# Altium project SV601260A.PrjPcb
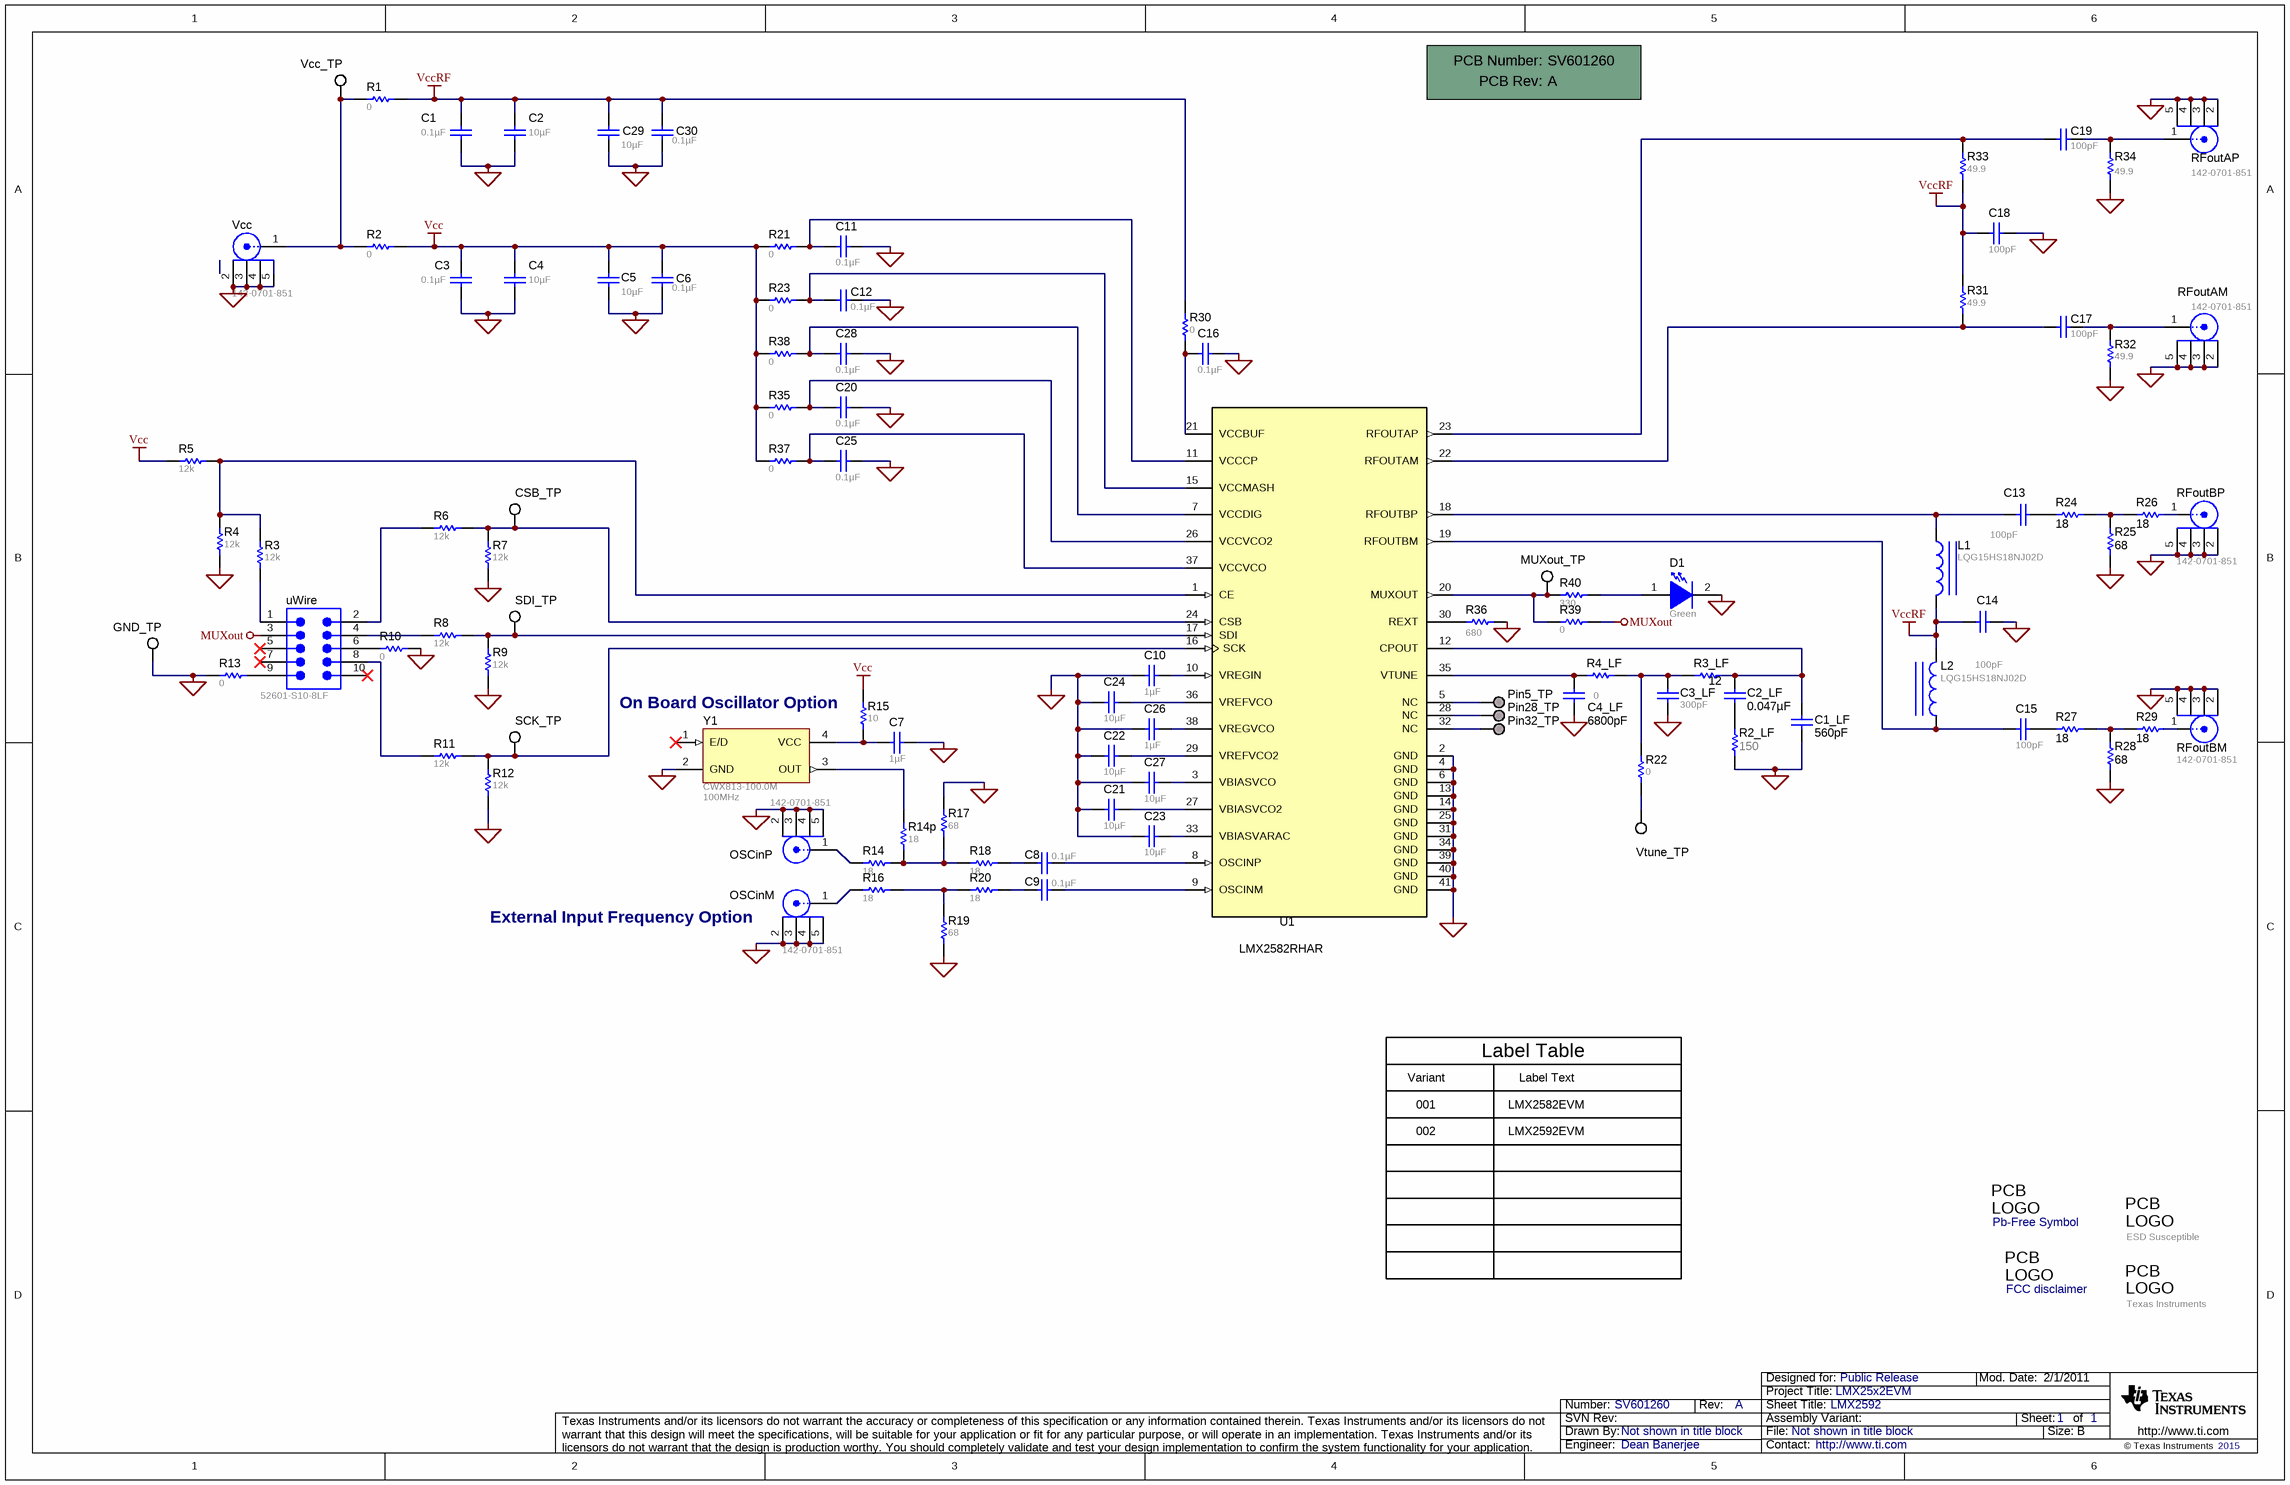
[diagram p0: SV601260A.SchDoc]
TechSupport: http://www.ti.com; SCH_Rev: A; PRJ_Title: LMX25x2EVM; PRJ_Number: SV601260; PRJ_Engineer: Dean Banerjee; PRJ_Customer: Public Release; PCB_Rev: A; PCB_Layout: Dean Banerjee; CopyrightYear: 2015
1 sheet, 106 parts. Net scope: global (net labels, ports and power ports of the same name join across sheets).
Board file: SV601260A.PcbDoc

## Sheet SV601260A.SchDoc: LMX2592
size 431 x 279 mm; Date: Not shown in title block; ApprovedBy: Not shown in title block; CheckedBy: Not shown in title block; Author: Not shown in title block; CompanyName: Not shown in title block; DrawnBy: Not shown in title block; Engineer: Not shown in title block; Organization: Not shown in title block; Address1: Not shown in title block; Address2: Not shown in title block; Address3: Not shown in title block; Address4: Not shown in title block; DocumentNumber: 1; Revision: Use project parameter SCH_Rev; SheetNumber: 1; SheetTotal: 1; PageSetup: Record=PageOptions¦CenterHorizontal=True¦CenterVertical=True¦PrintScale=0.72¦XCorrection=1.00¦YCorrection=1.00¦PrintKind=0¦BorderSize=5000000¦LeftOffset=0¦BottomOffset=0¦Orientation=2¦PaperLength=1000¦PaperWidth=1000¦Scale=100¦PaperSource=15¦PrintQuality=600¦MediaType=1¦DitherType=10¦PrintScaleMode=1¦PaperKind=Legal (8.5 x 14")¦PaperIndex=5

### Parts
!PCB  Printed Circuit Board  (value not drawn)  (mechanical)
C1  ValueDisplayed: 0.1µF  [0603]  (hidden comment: 0603YC104JAT2A)
C1_LF  ValueDisplayed: 560pF  [0603]  (hidden comment: C0603C561K5RACTU)
C2  ValueDisplayed: 10µF  [0805]  (hidden comment: C0805C106K8PACTU)
C2_LF  ValueDisplayed: 0.047µF  [0603]  (hidden comment: GRM188R71H473KA61D)
C3  ValueDisplayed: 0.1µF  [0603]  (hidden comment: 0603YC104JAT2A)
C3_LF  ValueDisplayed: 300pF  [0603]  (hidden comment: GRM1885C2A301JA01D)
C4  ValueDisplayed: 10µF  [0805]  (hidden comment: C0805C106K8PACTU)
C4_LF  ValueDisplayed: 6800pF  [0603]  (hidden comment: GRM188R71H682KA01D)
C5  ValueDisplayed: 10µF  [0805]  (hidden comment: C0805C106K8PACTU)
C6  ValueDisplayed: 0.1µF  [0603]  (hidden comment: 0603YC104JAT2A)
C7  ValueDisplayed: 1µF  [0603]  (hidden comment: C1608X7R1C105K)
C8  ValueDisplayed: 0.1µF  [0603L]  (hidden comment: 0603YC104JAT2A)
C9  ValueDisplayed: 0.1µF  [0603L]  (hidden comment: 0603YC104JAT2A)
C10  ValueDisplayed: 1µF  [0603L]  (hidden comment: C1608X7R1C105K)
C11  ValueDisplayed: 0.1µF  [0603L]  (hidden comment: 0603YC104JAT2A)
C12  ValueDisplayed: 0.1µF  [0603L]  (hidden comment: 0603YC104JAT2A)
C13  ValueDisplayed: 100pF  [0402]  (hidden comment: GRM1535C1H101JDD5D)
C14  ValueDisplayed: 100pF  [0402]  (hidden comment: GRM1535C1H101JDD5D)
C15  ValueDisplayed: 100pF  [0402]  (hidden comment: GRM1535C1H101JDD5D)
C16  ValueDisplayed: 0.1µF  [0603L]  (hidden comment: 0603YC104JAT2A)
C17  ValueDisplayed: 100pF  [0402]  (hidden comment: GRM1535C1H101JDD5D)
C18  ValueDisplayed: 100pF  [0402]  (hidden comment: GRM1535C1H101JDD5D)
C19  ValueDisplayed: 100pF  [0402]  (hidden comment: GRM1535C1H101JDD5D)
C20  ValueDisplayed: 0.1µF  [0603L]  (hidden comment: 0603YC104JAT2A)
C21  ValueDisplayed: 10µF  [0603]  (hidden comment: C1608X5R1A106M)
C22  ValueDisplayed: 10µF  [0603]  (hidden comment: C1608X5R1A106M)
C23  ValueDisplayed: 10µF  [0603]  (hidden comment: C1608X5R1A106M)
C24  ValueDisplayed: 10µF  [0603]  (hidden comment: C1608X5R1A106M)
C25  ValueDisplayed: 0.1µF  [0603]  (hidden comment: 0603YC104JAT2A)
C26  ValueDisplayed: 1µF  [0603]  (hidden comment: C1608X5R0J105K)
C27  ValueDisplayed: 10µF  [0603]  (hidden comment: C1608X5R1A106M)
C28  ValueDisplayed: 0.1µF  [0603L]  (hidden comment: 0603YC104JAT2A)
C29  ValueDisplayed: 10µF  [0805]  (hidden comment: C0805C106K8PACTU)
C30  ValueDisplayed: 0.1µF  [0603]  (hidden comment: 0603YC104JAT2A)
CSB_TP  5007  [Keystone5007]  (value not drawn)
D1  value Green  [LED_LTST-C190]  (hidden comment: LTST-C190GKT)
GND_TP  5007  [Keystone5007]  (value not drawn)
L1  LQG15HS18NJ02D  [IND_LQG15H]
L2  LQG15HS18NJ02D  [IND_LQG15H]
Logo1  ESD Susceptible  [ESD_Overlay_Small]  (no BOM)
Logo2  Texas Instruments  [TI_Stacked_Overlay_Small_Vertical]  (no BOM)
Logo3  Pb-Free Symbol  [Pb-Free_Overlay_Medium]  (no BOM)
Logo4  FCC disclaimer  [FCC_disclaimer]  (no BOM)
MUXout_TP  5007  [Keystone5007]  (value not drawn)
OSCinM  142-0701-851  [Emerson_142-0701-851]
OSCinP  142-0701-851  [Emerson_142-0701-851]
Pin5_TP  TESTPOINT  [TP_25MIL-SMT]  (value not drawn)  (no BOM)
Pin28_TP  TESTPOINT  [TP_25MIL-SMT]  (value not drawn)  (no BOM)
Pin32_TP  TESTPOINT  [TP_25MIL-SMT]  (value not drawn)  (no BOM)
R1  value 0  [0603]  (hidden comment: CRCW06030000Z0EA)
R2  value 0  [0603]  (hidden comment: CRCW06030000Z0EA)
R2_LF  ValueDisplayed: 150  [0603]  (hidden comment: CRCW0603150RJNEA)
R3  value 12k  [0603]  (hidden comment: CRCW060312K0JNEA)
R3_LF  ValueDisplayed: 12  [0603]  (hidden comment: CRCW060312R0JNEA)
R4  value 12k  [0603]  (hidden comment: CRCW060312K0JNEA)
R4_LF  value 0  [0603]  (hidden comment: CRCW06030000Z0EA)
R5  value 12k  [0603]  (hidden comment: CRCW060312K0JNEA)
R6  value 12k  [0603]  (hidden comment: CRCW060312K0JNEA)
R7  value 12k  [0603]  (hidden comment: CRCW060312K0JNEA)
R8  value 12k  [0603]  (hidden comment: CRCW060312K0JNEA)
R9  value 12k  [0603]  (hidden comment: CRCW060312K0JNEA)
R10  value 0  [0603]  (hidden comment: CRCW06030000Z0EA)
R11  value 12k  [0603]  (hidden comment: CRCW060312K0JNEA)
R12  value 12k  [0603]  (hidden comment: CRCW060312K0JNEA)
R13  value 0  [0603]  (hidden comment: CRCW06030000Z0EA)
R14  value 18  [0603]  (hidden comment: CRCW060318R0JNEA)
R14p  value 18  [0603]  (hidden comment: CRCW060318R0JNEA)
R15  value 10  [0603]  (hidden comment: CRCW060310R0JNEA)
R16  value 18  [0603]  (hidden comment: CRCW060318R0JNEA)
R17  value 68  [0603]  (hidden comment: CRCW060368R0JNEA)
R18  value 18  [0603]  (hidden comment: CRCW060318R0JNEA)
R19  value 68  [0603]  (hidden comment: CRCW060368R0JNEA)
R20  value 18  [0603]  (hidden comment: CRCW060318R0JNEA)
R21  value 0  [0603L]  (hidden comment: CRCW06030000Z0EA)
R22  value 0  [0603]  (hidden comment: CRCW06030000Z0EA)
R23  value 0  [0603L]  (hidden comment: CRCW06030000Z0EA)
R24  ValueDisplayed: 18  [0402]  (hidden comment: CRCW040218R0JNED)
R25  ValueDisplayed: 68  [0402L]  (hidden comment: CRCW040268R0JNED)
R26  ValueDisplayed: 18  [0402]  (hidden comment: CRCW040218R0JNED)
R27  ValueDisplayed: 18  [0402]  (hidden comment: CRCW040218R0JNED)
R28  ValueDisplayed: 68  [0402L]  (hidden comment: CRCW040268R0JNED)
R29  ValueDisplayed: 18  [0402]  (hidden comment: CRCW040218R0JNED)
R30  value 0  [0603L]  (hidden comment: CRCW06030000Z0EA)
R31  ValueDisplayed: 49.9  [0402L]  (hidden comment: CRCW040249R9FKED)
R32  ValueDisplayed: 49.9  [0402L]  (hidden comment: CRCW040249R9FKED)
R33  ValueDisplayed: 49.9  [0402L]  (hidden comment: CRCW040249R9FKED)
R34  ValueDisplayed: 49.9  [0402L]  (hidden comment: CRCW040249R9FKED)
R35  value 0  [0603L]  (hidden comment: CRCW06030000Z0EA)
R36  ValueDisplayed: 680  [0603]  (hidden comment: RC0603FR-07680RL)
R37  value 0  [0603]  (hidden comment: CRCW06030000Z0EA)
R38  value 0  [0603L]  (hidden comment: CRCW06030000Z0EA)
R39  value 0  [0603]  (hidden comment: CRCW06030000Z0EA)
R40  value 330  [0603]  (hidden comment: RC0603JR-07330RL)
RFoutAM  142-0701-851  [Emerson_142-0701-851]
RFoutAP  142-0701-851  [Emerson_142-0701-851]
RFoutBM  142-0701-851  [Emerson_142-0701-851]
RFoutBP  142-0701-851  [Emerson_142-0701-851]
SCK_TP  5007  [Keystone5007]  (value not drawn)
SDI_TP  5007  [Keystone5007]  (value not drawn)
U1  LMX2582RHAR  [RHA0040C]
uWire  52601-S10-8LF  [FCI_52601-S10-8LF]
Vcc  142-0701-851  [Emerson_142-0701-851]
Vcc_TP  5007  [Keystone5007]  (value not drawn)
Vtune_TP  5007  [Keystone5007]  (value not drawn)
Y1  CWX813-100.0M  Frequency: 100MHz  [OSC_CWX]

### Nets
GND: C1.1 C1_LF.2 C2.1 C3.1 C3_LF.2 C4.1 C4_LF.1 C5.1 C6.1 C7.2 C10.1 C11.1 C12.1 C14.1 C16.1 C18.1 C20.1 C21.2 C22.2 C23.2 C24.2 C25.1 C26.2 C27.1 C28.2 C29.1 C30.1 D1.2(K) GND_TP.1 OSCinM.2 OSCinM.3 OSCinM.4 OSCinM.5 OSCinP.2 OSCinP.3 OSCinP.4 OSCinP.5 R2_LF.2 R4.1 R7.1 R9.1 R10.1 R12.1 R13.2 R17.2 R19.1 R25.1 R28.2 R32.2 R34.1 R36.2 RFoutAM.2 RFoutAM.3 RFoutAM.4 RFoutAM.5 RFoutAP.2 RFoutAP.3 RFoutAP.4 RFoutAP.5 RFoutBM.2 RFoutBM.3 RFoutBM.4 RFoutBM.5 RFoutBP.2 RFoutBP.3 RFoutBP.4 RFoutBP.5 U1.2(GND) U1.4(GND) U1.6(GND) U1.13(GND) U1.14(GND) U1.25(GND) U1.31(GND) U1.34(GND) U1.39(GND) U1.40(GND) U1.41(GND) Vcc.2 Vcc.3 Vcc.4 Vcc.5 Y1.2(GND)
MUXout: R39.1 uWire.3
Vcc: C3.2 C4.2 C5.2 C6.2 R2.2 R5.1 R15.2 R21.1 R23.1 R35.2 R37.2 R38.1
VccRF: C1.2 C2.2 C14.2 C18.2 C29.2 C30.2 L1.2 L2.2 R1.2 R30.1 R31.2 R33.1
NetC1_LF_1: C1_LF.1 C2_LF.1 R3_LF.1 U1.12(CPOUT)
NetC2_LF_2: C2_LF.2 R2_LF.1
NetC3_LF_1: C3_LF.1 R3_LF.2 R4_LF.2 R22.1
NetC4_LF_2: C4_LF.2 R4_LF.1 U1.35(VTUNE)
NetC7_1: C7.1 R15.1 Y1.4(VCC)
NetC8_1: C8.1 R18.2
NetC8_2: C8.2 U1.8(OSCINP)
NetC9_1: C9.1 R20.1
NetC9_2: C9.2 U1.9(OSCINM)
NetC10_2: C10.2 U1.10(VREGIN)
NetC11_2: C11.2 R21.2 U1.11(VCCCP)
NetC12_2: C12.2 R23.2 U1.15(VCCMASH)
NetC13_1: C13.1 R24.2
NetC13_2: C13.2 L1.1 U1.18(RFOUTBP)
NetC15_1: C15.1 R27.2
NetC15_2: C15.2 L2.1 U1.19(RFOUTBM)
NetC16_2: C16.2 R30.2 U1.21(VCCBUF)
NetC17_1: C17.1 R32.1 RFoutAM.1
NetC17_2: C17.2 R31.1 U1.22(RFOUTAM)
NetC19_1: C19.1 R34.2 RFoutAP.1
NetC19_2: C19.2 R33.2 U1.23(RFOUTAP)
NetC20_2: C20.2 R35.1 U1.26(VCCVCO2)
NetC21_1: C21.1 U1.27(VBIASVCO2)
NetC22_1: C22.1 U1.29(VREFVCO2)
NetC23_1: C23.1 U1.33(VBIASVARAC)
NetC24_1: C24.1 U1.36(VREFVCO)
NetC25_2: C25.2 R37.1 U1.37(VCCVCO)
NetC26_1: C26.1 U1.38(VREGVCO)
NetC27_2: C27.2 U1.3(VBIASVCO)
NetC28_1: C28.1 R38.2 U1.7(VCCDIG)
NetCSB_TP_1: CSB_TP.1 R6.2 R7.2 U1.24(CSB)
NetD1_1: D1.1(A) R40.1
NetMUXout_TP_1: MUXout_TP.1 R39.2 R40.2 U1.20(MUXOUT)
NetOSCinM_1: OSCinM.1 R16.1
NetOSCinP_1: OSCinP.1 R14.1
NetPin5_TP_1: Pin5_TP.1 U1.5(NC)
NetPin28_TP_1: Pin28_TP.1 U1.28(NC)
NetPin32_TP_1: Pin32_TP.1 U1.32(NC)
NetR1_1: R1.1 R2.1 Vcc.1 Vcc_TP.1
NetR3_1: R3.1 uWire.1
NetR3_2: R3.2 R4.2 R5.2 U1.1(CE)
NetR6_1: R6.1 uWire.2
NetR8_1: R8.1 R9.2 SDI_TP.1 U1.17(SDI)
NetR8_2: R8.2 uWire.4
NetR10_2: R10.2 uWire.6
NetR11_1: R11.1 uWire.8
NetR11_2: R11.2 R12.2 SCK_TP.1 U1.16(SCK)
NetR13_1: R13.1 uWire.9
NetR14_2: R14.2 R14p.1 R17.1 R18.1
NetR14p_2: R14p.2 Y1.3(OUT)
NetR16_2: R16.2 R19.2 R20.2
NetR22_2: R22.2 Vtune_TP.1
NetR24_1: R24.1 R25.2 R26.2
NetR26_1: R26.1 RFoutBP.1
NetR27_1: R27.1 R28.1 R29.2
NetR29_1: R29.1 RFoutBM.1
NetR36_1: R36.1 U1.30(REXT)

Not connected (* = marked no-connect by the designer): uWire 5* 7* 10*; Y1 1(E/D)*

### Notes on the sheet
- On Board Oscillator Option
- (near OSCinM) External Input Frequency Option
- Variant
- 001
- Label Table
- Label Text
- LMX2582EVM
- 002
- LMX2592EVM

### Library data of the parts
!PCB = PCB: Manufacturer: Any; PartNumber: SV601260; SymbolCreator: a0412235
C1 C3 C6 C25 C30 = 0603YC104JAT2A: CAP, CERM, 0.1uF, 16V, +/-5%, X7R, 0603; Manufacturer: AVX; ESR_Ohm: 0.039; Polarized: N; TaMax_C: 125; TaMin_C: -55; Tolerance_%: 5; VDC_V: 16; Cap_F: 0.0000001; CompType: Capacitor; Value1: 0.039 ohm; U/M: EA
C1_LF = C0603C561K5RACTU: CAP, CERM, 560 pF, 50 V, +/- 10%, X7R, 0603; Manufacturer: Kemet; Polarized: N; TaMax_C: 125; TaMin_C: -55; Tolerance_%: 10; VDC_V: 50; Cap_F: 0.00000000056; CompType: Capacitor; Value: 560pF; Value1: Unknown; Value2: 50V; U/M: EA
C2 C4 C5 C29 = C0805C106K8PACTU: CAP, CERM, 10uF, 10V, +/-10%, X5R, 0805; Manufacturer: Kemet; ESR_Ohm: 0.003; IRMS_A: 11.43; Polarized: N; TaMax_C: 85; TaMin_C: -55; Tolerance_%: 10; Cap_F: 0.00001; CompType: Capacitor; U/M: EA; Value1: 0.003 ohm
C2_LF = GRM188R71H473KA61D: CAP, CERM, 0.047 µF, 50 V, +/- 10%, X7R, 0603; Manufacturer: MuRata; Polarized: N; TaMax_C: 125; TaMin_C: -55; Tolerance_%: 10; VDC_V: 50; Cap_F: 0.000000047; CompType: Capacitor; Value: 0.047uF; Value1: Unknown; Value2: 50V; U/M: EA
C3_LF = GRM1885C2A301JA01D: CAP, CERM, 300pF, 100V, +/-5%, C0G/NP0, 0603; Manufacturer: MuRata; Polarized: N; TaMax_C: 125; TaMin_C: -55; Tolerance_%: 5; VDC_V: 100; Cap_F: 0.0000000003; CompType: Capacitor; Value1: Unknown; U/M: EA
C4_LF = GRM188R71H682KA01D: CAP, CERM, 6800 pF, 50 V, +/- 10%, X7R, 0603; Manufacturer: MuRata; Polarized: N; TaMax_C: 125; TaMin_C: -55; Tolerance_%: 10; VDC_V: 50; Cap_F: 0.0000000068; CompType: Capacitor; Value: 6800pF; Value1: Unknown; Value2: 50V; U/M: EA
C7 = C1608X7R1C105K: CAP, CERM, 1uF, 16V, +/-10%, X7R, 0603; Manufacturer: TDK; ESR_Ohm: 0.0057; Polarized: N; TaMax_C: 125; TaMin_C: -55; Tolerance_%: 10; VDC_V: 16; Cap_F: 0.000001; CompType: Capacitor; U/M: EA; Value1: 0.0057 ohm
C8 C9 C11 C12 C16 C20 C28 = 0603YC104JAT2A: CAP, CERM, 0.1uF, 16V, +/-5%, X7R, 0603; Manufacturer: AVX; Cap_Case: 0603; ESR_Ohm: 0.039; Polarized: N; TaMax_C: 125; TaMin_C: -55; Tolerance_%: 5; VDC_V: 16; Cap_F: 0.0000001; CompType: Capacitor; Value1: 0.039 ohm; U/M: EA
C10 = C1608X7R1C105K: CAP, CERM, 1uF, 16V, +/-10%, X7R, 0603; Manufacturer: TDK; Polarized: N; CompType: Capacitor; U/M: EA; Cap_F: 0.000001; Tolerance_%: 10; ESR_Ohm: 0.0057; Value1: 0.0057 ohm; VDC_V: 16; TaMin_C: -55; TaMax_C: 125; Cap_Case: 0603
C13-C15 C17-C19 = GRM1535C1H101JDD5D: CAP, CERM, 100 pF, 50 V, +/- 5%, C0G/NP0, 0402; Manufacturer: MuRata; Polarized: N; CompType: Capacitor; Value: 100pF; U/M: EA; Cap_F: 0.0000000001; Tolerance_%: 5; Value1: Unknown; VDC_V: 50; Value2: 50V; TaMin_C: -55; TaMax_C: 125
C21-C24 C27 = C1608X5R1A106M: CAP, CERM, 10uF, 10V, +/-10%, C0G/NP0, 0603; Manufacturer: TDK; ESR_Ohm: 0.0078; IRMS_A: 1.85; Polarized: N; TaMax_C: 85; TaMin_C: -55; Tolerance_%: 10; Cap_F: 0.00001; CompType: Capacitor; U/M: EA; Value1: 0.0078 ohm
C26 = C1608X5R0J105K: CAP, CERM, 1 µF, 6.3 V, +/- 10%, X5R, 0603; Manufacturer: TDK; ESR_ohm: 0.0057; Polarized: N; TaMax_C: 85; TaMin_C: -55; Tolerance_%: 10; VDC_V: 6.3; Cap_F: 0.000001; CompType: Capacitor; Value: 1uF; U/M: EA; Value1: 0.0057 ohm; Value2: 6.3V
CSB_TP GND_TP MUXout_TP SCK_TP SDI_TP Vcc_TP Vtune_TP = 5007: Test Point, Compact, White, TH; Manufacturer: Keystone; CompType: Test Point Loop; U/M: EA
D1 = LTST-C190GKT: LED, Green, SMD; Manufacturer: Lite-On; Vf_V: 2.1; Value2: 2.1V; Io_A: 0.02; Power_TotalModule: 0.1; Value1: 0.1W; U/M: EA
L1 L2 = LQG15HS18NJ02D: Inductor, Multilayer, Air Core, 18 nH, 0.3 A, 0.36 ohm, SMD; Manufacturer: MuRata; Value: 18nH; Ind_H: 18.0E-9; Imax_A: 0.3; Irms: 0.3A @ C rise; Isat: 0.3A @ % inductance drop; DCR_ohm: 0.36; Value2: 0.3A
Logo1 = ESD_Susceptible: ESD Susceptible Symbol; SymbolCreator: codlsc
Logo2 = TI_Logo: Texas Instrument Corporate Signature; SymbolCreator: codlsc
Logo3 = Pb-Free: SymbolCreator: a0412235
Logo4 = FCC_disclaimer: SymbolCreator: codlsc
OSCinM OSCinP RFoutAM RFoutAP RFoutBM RFoutBP Vcc = 142-0701-851: Connector, SMT, End launch SMA 50 ohm; Manufacturer: Emerson Network Power Connectivity; U/M: EA
Pin5_TP Pin28_TP Pin32_TP = TESTPOINT: TEST POINT.  No entry in BOM.
R1 R2 R4_LF R10 R13 R21-R23 R30 R35 R37-R39 = CRCW06030000Z0EA: RES, 0 ohm, 5%, 0.1W, 0603; Manufacturer: Vishay-Dale; CompType: Resistor; Tolerance_%: 5; VDC_V: 75; Power_W: 0.1; U/M: EA; Value_Code: 0000; EIA_Code: E24
R2_LF = CRCW0603150RJNEA: RES, 150, 5%, 0.1 W, 0603; Manufacturer: Vishay-Dale; CompType: Resistor; Tolerance_%: 5; VDC_V: 75; Power_W: 0.1; Value: 150; U/M: EA; Value_Code: 150R; Value2: 0.1W; TempCo: 200 ppm/C; EIA_Code: E24
R3-R9 R11 R12 = CRCW060312K0JNEA: RES, 12k ohm, 5%, 0.1W, 0603; Manufacturer: Vishay-Dale; CompType: Resistor; Tolerance_%: 5; VDC_V: 75; Power_W: 0.1; Res_ohm: 12000; U/M: EA; Value_Code: 12k0; EIA_Code: E24
R3_LF = CRCW060312R0JNEA: RES, 12, 5%, 0.1 W, 0603; Manufacturer: Vishay-Dale; CompType: Resistor; Tolerance_%: 5; VDC_V: 75; Power_W: 0.1; Value: 12; U/M: EA; Value_Code: 12R0; Value2: 0.1W; EIA_Code: E24; TempCo: 200 ppm/C
R14 R14p R16 R18 R20 = CRCW060318R0JNEA: RES, 18 ohm, 5%, 0.1W, 0603; Manufacturer: Vishay-Dale; CompType: Resistor; Tolerance_%: 5; VDC_V: 75; Power_W: 0.1; U/M: EA; Value_Code: 18R0; EIA_Code: E24
R15 = CRCW060310R0JNEA: RES, 10 ohm, 5%, 0.1W, 0603; Manufacturer: Vishay-Dale; CompType: Resistor; Value_Code: 10R0; Tolerance_%: 5; Power_W: 0.1; VDC_V: 75; TempCo: 200 ppm/C; EIA_Code: E24; U/M: EA
R17 R19 = CRCW060368R0JNEA: RES, 68 ohm, 5%, 0.1W, 0603; Manufacturer: Vishay-Dale; CompType: Resistor; Value_Code: 68R0; Tolerance_%: 5; Power_W: 0.1; VDC_V: 75; TempCo: 200 ppm/C; EIA_Code: E24; U/M: EA
R24 R26 R27 R29 = CRCW040218R0JNED: RES, 18, 5%, 0.063 W, 0402; Manufacturer: Vishay-Dale; CompType: Resistor; Value: 18; Value_Code: 18R0; Tolerance_%: 5; Power_W: 0.063; Value2: 0.063W; VDC_V: 50; TempCo: 200 ppm/C; EIA_Code: E24; U/M: EA
R25 R28 = CRCW040268R0JNED: RES, 68, 5%, 0.063 W, 0402; Manufacturer: Vishay-Dale; CompType: Resistor; Value: 68; Value_Code: 68R0; Tolerance_%: 5; Power_W: 0.063; Value2: 0.063W; VDC_V: 50; TempCo: 200 ppm/C; EIA_Code: E24; U/M: EA
R31-R34 = CRCW040249R9FKED: RES, 49.9, 1%, 0.063 W, 0402; Manufacturer: Vishay-Dale; CompType: Resistor; Value: 49.9; Value_Code: 49R9; Tolerance_%: 1; Power_W: 0.063; Value2: 0.063W; VDC_V: 50; TempCo: 100 ppm/C; EIA_Code: E96; U/M: EA
R36 = RC0603FR-07680RL: RES, 680, 1%, 0.1 W, 0603; Manufacturer: Yageo America; CompType: Resistor; Value: 680; Value_Code: 680R; Tolerance_%: 1; Power_W: 0.1; Value2: 0.1W; VDC_V: 150; TempCo: 200 ppm/C; U/M: EA
R40 = RC0603JR-07330RL: RES, 330 ohm, 5%, 0.1W, 0603; Manufacturer: Yageo America; CompType: Resistor; Tolerance_%: 5; VDC_V: 50; Power_W: 0.1; U/M: EA; Value_Code: 330R; EIA_Code: E24
U1 = LMX2582RHAR: High Performance, Wideband PLLatinum RF Synthesizer, RHA0040C; Alternate PartNumber: LMX2582RHAT; Manufacturer: Texas Instruments; SymbolCreator: Altium; CompType: IC; U/M: EA
uWire = 52601-S10-8LF: Header (shrouded), 100mil, 5x2, Gold plated, SMD; Manufacturer: FCI; SymbolCreator: a0412235; U/M: EA
Y1 = CWX813-100.0M: OSC 100.0000MHZ 3.3V +-25PPM SMD; Manufacturer: Connor-Winfield; SymbolCreator: a0411947; CompType: Crystal; U/M: EA; TaMin_C: -20; TaMax_C: 70; Frequency Stability: ±25ppm

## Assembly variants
001: not fitted C3_LF R3 R4 R8 R11 R15 R16 R33 R35 R44
002: not fitted C3_LF R3 R4 R8 R11 R15 R16 R33 R35 R44; alternate parts U1 -> LMX2592RHAR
